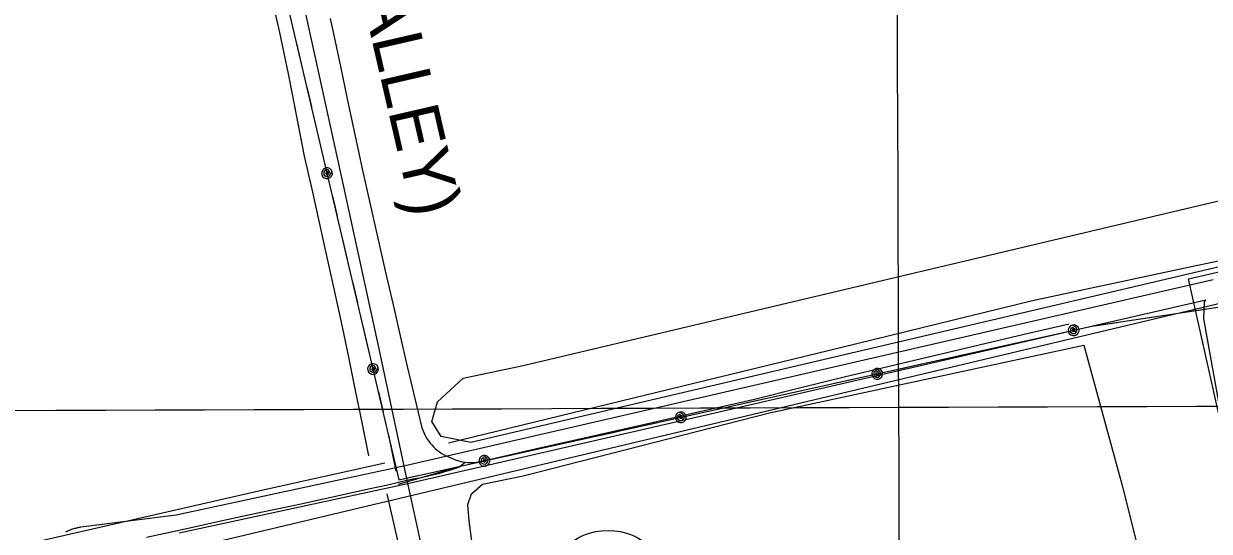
# Model space of a CAD drawing. Extents: x 3392644 to 3430565, y 576657 to 602123.
# Drawn here: x 3416383 to 3418352, y 587973 to 588816 of the extents above; entities that cross this region are included whole.
import ezdxf

# ---------------------------------------------------------------- set-up
doc = ezdxf.new("R2010")
doc.units = 0
for name, color, linetype in [('V-DOMW-TANK', 7, 'Continuous'), ('V-DTCH-CNTR', 7, 'Continuous'), ('V-GRID-MAJR', 7, 'Continuous'), ('V-RAIL-IDEN', 7, 'Continuous'), ('V-RAIL-TRAK', 7, 'Continuous'), ('V-ROAD-CNTR', 7, 'Continuous'), ('V-SITE-OTLN', 7, 'Continuous'), ('V-SITE-VEGE', 7, 'Continuous'), ('V-TOPO-BNDY', 7, 'Continuous'), ('V-TOPO-SHOR', 7, 'Continuous'), ('V-UTIL-LINE', 7, 'Continuous')]:
    doc.layers.add(name, color=color, linetype=linetype)

msp = doc.modelspace()

# ---------------------------------------------------------------- linework, layer by layer
at = {"layer": 'V-DOMW-TANK'}
msp.add_circle((3417353.5012444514, 587870.5058617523), 104.08091035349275, dxfattribs=at)
at = {"layer": 'V-DTCH-CNTR'}
for points in [[(3416956.1350000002, 588098.502), (3416945.114, 588153.978), (3416933.883, 588209.409), (3416922.4390000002, 588264.797), (3416910.784, 588320.142), (3416898.915, 588375.442), (3416886.8340000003, 588430.6950000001), (3416874.544, 588485.901), (3416862.041, 588541.06), (3416849.329, 588596.172), (3416842.983, 588630.41), (3416836.4450000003, 588664.6140000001), (3416829.716, 588698.779), (3416822.793, 588732.907), (3416815.683, 588766.995), (3416808.378, 588801.046), (3416800.884, 588835.053)], [(3416892.4560000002, 588824.5750000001), (3416897.449, 588801.779), (3416909.201, 588745.029), (3416921.142, 588688.317), (3416933.275, 588631.647), (3416945.594, 588575.018), (3416958.105, 588518.432), (3416970.802, 588461.889), (3416983.69, 588405.386), (3416996.769, 588348.929), (3417008.414, 588297.87), (3417020.278, 588246.861), (3417032.357, 588195.902), (3417044.6550000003, 588144.997), (3417046.009, 588141.082), (3417047.568, 588137.242), (3417049.327, 588133.49), (3417051.2830000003, 588129.836), (3417053.429, 588126.2930000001), (3417055.757, 588122.867), (3417058.2660000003, 588119.567), (3417060.943, 588116.405), (3417063.786, 588113.3910000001), (3417066.784, 588110.53), (3417069.928, 588107.83), (3417073.208, 588105.301), (3417076.62, 588102.9500000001), (3417080.151, 588100.779), (3417083.79, 588098.801), (3417087.5300000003, 588097.017), (3417091.36, 588095.434), (3417095.267, 588094.053), (3417098.593, 588092.501), (3417102.001, 588091.133), (3417105.481, 588089.955), (3417109.018, 588088.974), (3417112.606, 588088.1900000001), (3417116.231, 588087.606), (3417119.882, 588087.225), (3417123.5500000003, 588087.047), (3417127.22, 588087.072)], [(3417127.22, 588087.072), (3417130.886, 588087.299), (3417134.532, 588087.731), (3417138.149, 588088.3640000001), (3417141.724, 588089.198), (3417232.744, 588109.729), (3417323.7460000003, 588130.332), (3417414.735, 588151.002), (3417505.707, 588171.742), (3417596.665, 588192.552), (3417671.126, 588211.011), (3417745.643, 588229.258), (3417820.208, 588247.2930000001), (3417894.827, 588265.113), (3417969.495, 588282.719), (3418044.214, 588300.115), (3418118.983, 588317.296)], [(3417019.418, 588058.134), (3417030.014, 588059.936), (3417040.572, 588061.953), (3417051.086, 588064.187), (3417061.551, 588066.635), (3417071.963, 588069.295), (3417082.318, 588072.166), (3417092.613, 588075.251), (3417095.892, 588076.045), (3417099.11, 588077.067), (3417102.245, 588078.312), (3417105.288, 588079.773), (3417108.223, 588081.4400000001), (3417111.0330000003, 588083.308), (3417113.7060000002, 588085.368), (3417116.231, 588087.606)], [(3416587.345, 587963.201), (3416651.429, 587977.414), (3416715.558, 587991.422), (3416779.73, 588005.228), (3416843.9450000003, 588018.83), (3416881.327, 588026.979), (3416918.683, 588035.255), (3416956.014, 588043.66), (3416971.937, 588046.951), (3416987.8170000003, 588050.462), (3417003.646, 588054.189), (3417019.418, 588058.134)]]:
    msp.add_lwpolyline(points, dxfattribs=at)
at = {"layer": 'V-GRID-MAJR'}
for points in [[(3417859.292, 582120.98), (3417836.383, 588179.004), (3417813.4620000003, 594240.1140000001), (3417790.541, 600301.242), (3417790.529, 600304.306)], [(3396759.069, 588105.428), (3402028.4020000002, 588122.6730000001), (3407297.732, 588140.684), (3412567.059, 588159.461), (3417836.383, 588179.004), (3423105.705, 588199.314), (3428375.023, 588220.3910000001), (3428375.024, 588220.3910000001)]]:
    msp.add_spline(points, degree=3, dxfattribs=at)
at = {"layer": 'V-RAIL-TRAK'}
msp.add_lwpolyline([(3416192.597, 590596.707), (3416262.3540000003, 590474.978), (3416336.012, 590332.644), (3416413.347, 590175.192), (3416444.896, 590104.444), (3416475.932, 590034.8470000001), (3416556.703, 589838.446), (3416621.203, 589666.416), (3416682.344, 589486.919), (3416749.61, 589262.476), (3416802.573, 589049.001), (3416811.861, 589011.564), (3416866.719, 588762.179), (3416909.6350000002, 588565.4400000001), (3416972.856, 588276.088), (3417019.418, 588058.134), (3417070.958, 587822.036), (3417121.963, 587592.037), (3417123.169, 587586.438)], dxfattribs=at)
at = {"layer": 'V-ROAD-CNTR'}
for points in [[(3416636.5706890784, 588000.1159733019), (3417016.5869290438, 588082.482808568), (3418357.965246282, 588391.1311912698)], [(3416641.638678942, 587970.5180324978), (3417023.1289159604, 588053.2048671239), (3418345.912270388, 588357.5732583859)], [(3418375.032212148, 588147.6546782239), (3418342.505277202, 588325.9293216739), (3418343.739274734, 588353.9212656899), (3418345.912270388, 588357.5732583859)], [(3416460.773040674, 587975.4740225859), (3416461.20003982, 587975.643022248), (3416463.0270361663, 587976.3210208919), (3416464.793032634, 587976.9340196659), (3416466.499029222, 587977.4890185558), (3416468.163025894, 587977.994017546), (3416469.777022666, 587978.4460166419), (3416471.333019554, 587978.849015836), (3416472.857016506, 587979.2100151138), (3416474.342013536, 587979.5280144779), (3416475.7770106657, 587979.8040139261), (3416477.1700078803, 587980.0400134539), (3416478.499005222, 587980.2360130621), (3416636.5706890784, 588000.1159733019)], [(3416453.43005536, 587972.28702896), (3416455.453051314, 587973.233027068), (3416457.419047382, 587974.1050253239), (3416459.3360435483, 587974.9070237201), (3416460.773040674, 587975.4740225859)]]:
    msp.add_lwpolyline(points, dxfattribs=at)
at = {"layer": 'V-SITE-OTLN'}
msp.add_lwpolyline([(3418381.9930000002, 588103.329), (3418317.072, 588392.281), (3419057.708, 588561.968), (3419062.58, 588541.505), (3419157.085, 588144.526), (3418472.6520000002, 588010.294), (3418448.967, 588118.679)], close=True, dxfattribs=at)
msp.add_lwpolyline([(3417158.137, 587722.62), (3417123.0300000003, 587990.484), (3417120.79, 588017.475), (3417126.8370000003, 588035.026), (3417144.9620000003, 588051.5700000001), (3417212.481, 588065.256), (3417621.548, 588169.743), (3418143.4990000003, 588282.263), (3418207.2660000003, 588049.053), (3418241.011, 587914.659)], dxfattribs=at)
at = {"layer": 'V-SITE-VEGE'}
msp.add_lwpolyline([(3419090.278, 588581.625), (3417125.521, 588120.352), (3417076.579, 588130.366), (3417061.072, 588155.571), (3417070.491, 588188.069), (3417113.038, 588227.556), (3417212.432, 588248.524), (3418804.235, 588625.018), (3419575.365, 588810.071), (3419632.512, 588799.753), (3419631.306, 588766.952), (3419605.776, 588743.263), (3419530.702, 588713.184)], close=True, dxfattribs=at)
at = {"layer": 'V-TOPO-BNDY'}
msp.add_line((3414370.3243064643, 587401.4639773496), (3421544.912, 589106.4129999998), dxfattribs=at)
at = {"layer": 'V-TOPO-SHOR'}
for points in [[(3417088.786, 588119.844), (3417741.835, 588278.822), (3418057.981, 588356.158), (3418308.894, 588410.121), (3418594.164, 588470.015), (3418889.578, 588539.352), (3419154.165, 588599.143), (3419465.301, 588670.256), (3419572.792, 588690.48)], [(3416180.96, 587903.108), (3416393.647, 587953.618), (3416783.036, 588042.622), (3416982.8140000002, 588086.957)], [(3416986.395600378, 588035.5064562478), (3417109.7382328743, 587493.8224618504), (3417175.5876606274, 587186.5837731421), (3417249.5971630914, 586860.4945201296), (3417263.3182457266, 586795.8121747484)]]:
    msp.add_lwpolyline(points, dxfattribs=at)
at = {"layer": 'V-UTIL-LINE'}
for points in [[(3417186.864, 600288.879), (3415306.279, 597067.023), (3413990.571, 594815.96), (3413738.896, 594367.605), (3414019.188, 594062.863), (3414329.554, 593576.738), (3414657.473, 593049.707), (3414990.376, 592512.957), (3415312.202, 591995.327), (3416131.577, 590652.721), (3416386.4220000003, 590188.311), (3416495.035, 589926.031), (3416596.258, 589669.814), (3416757.253, 589120.116), (3417006.473, 588058.733), (3418156.504, 588313.401), (3418409.933, 588351.9130000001)], [(3416836.465, 588782.7660000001), (3416844.237, 588749.666)], [(3416853.38, 588710.726), (3416861.1520000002, 588677.626)], [(3416870.296, 588638.685), (3416878.068, 588605.585)], [(3416886.977, 588567.644), (3416888.906, 588569.779), (3416886.597, 588570.067), (3416884.808, 588567.983), (3416885.789, 588565.225), (3416889.13, 588565.844), (3416891.696, 588569.767), (3416889.078, 588573.137), (3416884.219, 588573.3250000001), (3416881.616, 588569.558), (3416881.669, 588565.088), (3416885.5100000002, 588562.17), (3416890.934, 588563.112), (3416895.739, 588569.702), (3416894.285, 588572.898), (3416891.718, 588575.294), (3416888.429, 588576.526), (3416884.92, 588576.406), (3416881.724, 588574.952), (3416879.327, 588572.385), (3416878.095, 588569.096), (3416878.215, 588565.587), (3416879.67, 588562.3910000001), (3416882.236, 588559.9940000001), (3416885.525, 588558.762), (3416889.034, 588558.883), (3416892.231, 588560.337), (3416894.627, 588562.903), (3416895.859, 588566.192), (3416895.739, 588569.702)], [(3416895.898, 588529.65), (3416903.67, 588496.55)], [(3416912.8140000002, 588457.609), (3416920.586, 588424.509)], [(3416929.7290000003, 588385.569), (3416937.501, 588352.469)], [(3418311.112, 588336.8960000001), (3418344.7260000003, 588342.004)], [(3416946.645, 588313.528), (3416954.417, 588280.428)], [(3418126.5810000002, 588306.775), (3418124.471, 588308.731), (3418124.154, 588306.426), (3418126.214, 588304.61), (3418128.985, 588305.556), (3418128.409, 588308.904), (3418124.518, 588311.52), (3418121.115, 588308.9450000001), (3418120.865, 588304.088), (3418124.599, 588301.438), (3418129.069, 588301.434), (3418132.036, 588305.238), (3418131.163, 588310.674), (3418124.6350000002, 588315.562), (3418121.42, 588314.148), (3418118.991, 588311.612), (3418117.718, 588308.339), (3418117.794, 588304.829), (3418119.207, 588301.6140000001), (3418121.7430000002, 588299.185), (3418125.0160000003, 588297.912), (3418128.5270000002, 588297.988), (3418131.741, 588299.401), (3418134.17, 588301.937), (3418135.444, 588305.21), (3418135.3680000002, 588308.721), (3418133.954, 588311.935), (3418131.418, 588314.3640000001), (3418128.146, 588315.638), (3418124.6350000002, 588315.562)], [(3418164.793, 588314.661), (3418198.407, 588319.769)], [(3418237.953, 588325.779), (3418271.5670000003, 588330.887)], [(3418055.339, 588290.998), (3418088.535, 588298.349)], [(3417983.089, 588274.998), (3418016.285, 588282.349)], [(3417910.84, 588258.9990000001), (3417944.036, 588266.35)], [(3416963.326, 588242.4890000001), (3416965.255, 588244.623), (3416962.946, 588244.911), (3416961.157, 588242.828), (3416962.1380000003, 588240.069), (3416965.4790000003, 588240.688), (3416968.045, 588244.611), (3416965.427, 588247.981), (3416960.5670000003, 588248.169), (3416957.964, 588244.403), (3416958.018, 588239.932), (3416961.858, 588237.014), (3416967.2830000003, 588237.956), (3416972.088, 588244.546), (3416970.634, 588247.742), (3416968.0670000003, 588250.139), (3416964.778, 588251.371), (3416961.269, 588251.25), (3416958.072, 588249.796), (3416955.676, 588247.229), (3416954.444, 588243.941), (3416954.5640000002, 588240.431), (3416956.018, 588237.235), (3416958.585, 588234.838), (3416961.8740000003, 588233.606), (3416965.383, 588233.727), (3416968.579, 588235.181), (3416970.9760000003, 588237.748), (3416972.208, 588241.036), (3416972.088, 588244.546)], [(3417800.482, 588234.562), (3417798.372, 588236.518), (3417798.055, 588234.213), (3417800.115, 588232.397), (3417802.886, 588233.343), (3417802.309, 588236.691), (3417798.419, 588239.307), (3417795.0160000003, 588236.732), (3417794.7660000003, 588231.876), (3417798.5, 588229.225), (3417802.97, 588229.2220000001), (3417805.937, 588233.025), (3417805.0640000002, 588238.461), (3417798.536, 588243.349), (3417795.321, 588241.936), (3417792.892, 588239.399), (3417791.619, 588236.127), (3417791.694, 588232.616), (3417793.108, 588229.402), (3417795.644, 588226.9720000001), (3417798.917, 588225.699), (3417802.427, 588225.775), (3417805.642, 588227.188), (3417808.071, 588229.724), (3417809.345, 588232.997), (3417809.269, 588236.508), (3417807.855, 588239.7220000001), (3417805.319, 588242.151), (3417802.046, 588243.425), (3417798.536, 588243.349)], [(3417838.59, 588242.9990000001), (3417871.786, 588250.35)], [(3417729.239, 588218.783), (3417762.435, 588226.134)], [(3416972.247, 588204.493), (3416980.019, 588171.393)], [(3417656.989, 588202.784), (3417690.185, 588210.135)], [(3417512.49, 588170.786), (3417545.686, 588178.137)], [(3417584.74, 588186.785), (3417617.936, 588194.136)], [(3417474.382, 588162.349), (3417472.273, 588164.305), (3417471.9560000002, 588162), (3417474.0160000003, 588160.184), (3417476.787, 588161.13), (3417476.21, 588164.479), (3417472.3200000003, 588167.094), (3417468.917, 588164.52), (3417468.667, 588159.6630000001), (3417472.4, 588157.012), (3417476.8710000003, 588157.009), (3417479.838, 588160.812), (3417478.965, 588166.248), (3417472.437, 588171.136), (3417469.222, 588169.723), (3417466.793, 588167.187), (3417465.52, 588163.914), (3417465.595, 588160.403), (3417467.009, 588157.189), (3417469.545, 588154.76), (3417472.818, 588153.486), (3417476.328, 588153.562), (3417479.543, 588154.975), (3417481.972, 588157.511), (3417483.245, 588160.784), (3417483.17, 588164.295), (3417481.756, 588167.509), (3417479.22, 588169.938), (3417475.947, 588171.212), (3417472.437, 588171.136)], [(3417330.889, 588130.572), (3417364.085, 588137.9230000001)], [(3417403.139, 588146.571), (3417436.335, 588153.922)], [(3416989.163, 588132.452), (3417000.982, 588072.737)], [(3417258.64, 588114.573), (3417291.836, 588121.924)], [(3417148.2830000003, 588090.136), (3417146.174, 588092.0920000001), (3417145.856, 588089.787), (3417147.917, 588087.9720000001), (3417150.688, 588088.917), (3417150.111, 588092.2660000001), (3417146.221, 588094.881), (3417142.818, 588092.307), (3417142.568, 588087.4500000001), (3417146.301, 588084.799), (3417150.772, 588084.796), (3417153.739, 588088.599), (3417152.866, 588094.035), (3417146.338, 588098.9230000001), (3417143.123, 588097.51), (3417140.694, 588094.974), (3417139.42, 588091.701), (3417139.4960000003, 588088.1900000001), (3417140.91, 588084.976), (3417143.446, 588082.547), (3417146.719, 588081.273), (3417150.2290000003, 588081.349), (3417153.444, 588082.762), (3417155.873, 588085.299), (3417157.146, 588088.571), (3417157.0700000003, 588092.082), (3417155.657, 588095.296), (3417153.1210000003, 588097.726), (3417149.848, 588098.9990000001), (3417146.338, 588098.9230000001)], [(3417186.39, 588098.574), (3417219.586, 588105.925)], [(3417005.6920000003, 588051.326), (3417110.235, 588081.71)], [(3417006.079, 588060.412), (3417006.473, 588058.733), (3417037.985, 588065.711)]]:
    msp.add_lwpolyline(points, dxfattribs=at)

# ---------------------------------------------------------------- texts
at = {"layer": 'V-RAIL-IDEN'}
msp.add_text('VALLEY)', height=82.99983200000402, rotation=282.97998044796, dxfattribs=at).set_placement((3416927.248642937, 588935.9527541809))

doc.saveas('drawing.dxf')
